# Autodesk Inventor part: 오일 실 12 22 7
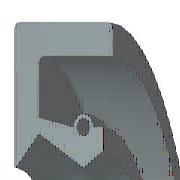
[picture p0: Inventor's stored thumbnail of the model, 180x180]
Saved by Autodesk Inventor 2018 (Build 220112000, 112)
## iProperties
IsCustomPart: 1
Created: 2012-02
Part Number: 오일 실 12 22 7
Material: 고무
Description: 오일-실
Document SubType Name: Modeling
Standard: KS B 2804
Designer: mduedu
Standards Organization: KS
Language: ko-KR
Size Designation: D - 12 22 7
Categories: <MemberInstance><Categories><Category DisplayName="샤프트 부품" InternalName="7f7aeb1f-a693-4053-b835-cee3144e0d98" Mnemonic="SHFT"><Category DisplayName="실링" Intern
Density: 0.93 g/cm^3
Mass: 1.25383 g
Surface Area: 18.4996 cm^2
Volume: 1.3482 cm^3
Appearance: 고무 - 검은색 - 버전 1.1
Author: mduedu
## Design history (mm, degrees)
revolve "본체" stored, may be unused: angle "d17" = 90 deg
revolve "스프링1" stored, may be unused: angle "d18" = 90 deg
body "Solid1"
sketch "스케치1"
  geometry: L1 (0, 11)-(7, 11); L2 (7, 9.25)-(1.75, 9.25); L3 (1.75, 7.75)-(4.9, 6); L4 (4.9, 6)-(0, 6); L5 (0, 0)-(9.586, 0) reference; L6 (4.9, 6)-(6.3, 6.875); L7 (0, 18)-(0, -3) reference; L8 (-1.941, 0)-(11.507, 0) reference; L9 (4.2, 8.1)-(1.75, 8.59); L10 (1.75, 8.59)-(1.75, 9.25); L11 (0, 11)-(0, 6.088); L12 (4.9, 6)-(0, 6); L13 (1.75, 7.75)-(0.152, 6.028); L14 (7, 11)-(7, 9.25); L15 (5.6, 8.1)-(6.3, 8.1); L16 (6.3, 8.1)-(6.3, 6.875); C1 r 0.455 at (4.9, 8.1); A1 r 0.7 centre (4.9, 8.1) between (5.6, 8.1) and (4.2, 8.1); A2 r 0.088 centre (0.088, 6.088) between (0, 6.088) and (0.152, 6.028); 1 further point
  constraints: 28 end point, 5 horizontal alignment, 5 point on line, 4 point on circle, 4 vertical alignment, 3 centre point, 3 tangent, 2 collinear, 2 horizontal, 2 perpendicular, 1 coincident, 1 parallel
  dimensions: "d0" = 22 diameter of L1 L5 (= SD2); "d1" = 1.75 distance of L1.end L2.start (= SD); "d2" = 0.91 diameter of C1 (= SPDI); "d3" = 1.4 diameter of A1 (= SPDA); "d4" = 12 diameter of L3.end L5 (= NND); "d5" = 15.5 diameter of L3.start L5 (= TKDM); "d7" = 17.18 diameter of L9.end L5 (= TKDM + 0.24 x SWDT); "d8" = 1.75 distance between parallel lines of L11 L10 (= SD); "d9" = 4.9 distance from line of L11 C1.centre (= SPDST); "d10" = 16.2 diameter of C1.centre L5 (= HLDM); "d11" = 0.0875 radius of A2 (= 0.25 x LAB); "d12" = 6.3 distance between parallel lines of L11 L16 (= SDI); "d13" = 13.75 diameter of L6.end L5 (= ABDM); "d14" = 7 distance from line of L11 L1.end (= SWDT)
fillet "모깎기1" dims "d6" = 0.3 (= RR)
other parameters: "SD2" = 22 [user parameter; used in 1 equation term], "SWDT" = 7 [user parameter; used in 2 equation terms], "RR" = 0.3 [user parameter; used in 1 equation term], "SD" = 1.75 [user parameter; used in 2 equation terms], "NND" = 12 [user parameter; used in 1 equation term], "SPDA" = 1.4 [user parameter; used in 1 equation term], "SPDI" = 0.91 [user parameter; used in 1 equation term], "TKDM" = 15.5 [user parameter; used in 2 equation terms], "HLDM" = 16.2 [user parameter; used in 1 equation term], "ABDM" = 13.75 [user parameter; used in 1 equation term], "SDI" = 6.3 [user parameter; used in 1 equation term], "SPDST" = 4.9 [user parameter; used in 1 equation term], "LAB" = 0.35 [user parameter; used in 1 equation term], "d15" = 0, "d16" = 0, "d19" = 0
